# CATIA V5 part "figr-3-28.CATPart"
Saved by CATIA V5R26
Part number: Part1
Bounding box of the stored display mesh (mm): x 0 to 71.72, y -62.404 to 71.526, z 0 to 0
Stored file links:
  D:\_Deepak\CATIA\CATIA V5-6R2016_Deepak\Resources\Part files\Partfiles\c03_catia_v5_6r2016_prt\figr-3-28.CATPart
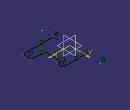
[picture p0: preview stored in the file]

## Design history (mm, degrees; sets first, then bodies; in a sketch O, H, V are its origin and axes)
Body1 (main body)
  Sketch1 on xy-plane, origin (0, 0, 0), H (1, 0, 0), V (0, 1, 0)
    axis line L1 (0, 71.5261) -> (1.8602, -62.4039)
    point P1 (0, 71.5261)
    line L2 (0.4896, 36.2738) -> (51.465, 36.2738)
    point P3 (0.4896, 36.2738)
    line L3 (51.465, 36.2738) -> (51.465, 23.0127)
    line L4 (51.465, 23.0127) -> (41.544, 23.0127)
    line L5 (41.544, 23.0127) -> (41.544, -16.3784)
    line L6 (41.544, -16.3784) -> (71.7203, -16.3784)
    line L7 (71.7203, -16.3784) -> (71.7203, -36.696)
    line L8 (71.7203, -36.696) -> (1.5031, -36.696)
    point P10 (1.5031, -36.696)
    coincidence: P1 V, P3 L1, P10 L1
    horizontal: L2 H, L4 H, L6 H, L8 H
    vertical: L3 V, L5 V, L7 V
